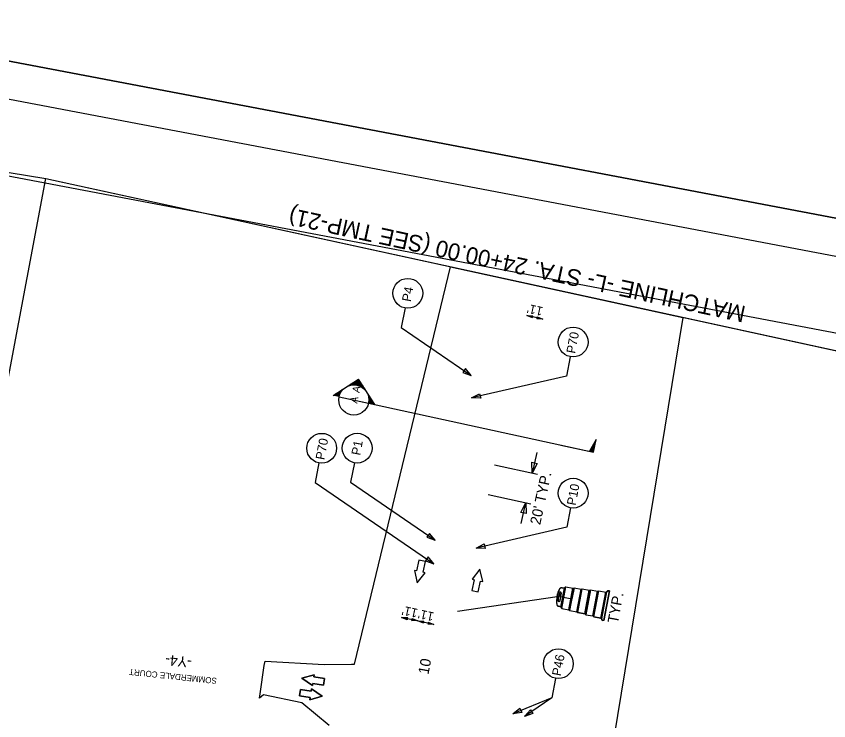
# Model space of a CAD drawing. Extents: x 1615680 to 1617075, y 898420 to 901168.
# Drawn here: x 1616157 to 1616696, y 900701 to 901168 of the extents above; entities that cross this region are included whole.
import ezdxf

# ---------------------------------------------------------------- set-up
doc = ezdxf.new("R2010")
doc.units = 0
for name, color, linetype in [('Default', 7, 'Continuous'), ('DEV BORDER CELL', 7, 'Continuous'), ('DEV DIRECTION OF TRAFFIC FLOW ARROW CELL', 7, 'Continuous'), ('DEV DRUM SECTIONAL VIEW CELL', 7, 'Continuous'), ('Matchline', 7, 'Continuous'), ('Matchline Text', 7, 'Continuous'), ('Old_Level_11', 7, 'Continuous'), ('Prop DSN Text', 7, 'Continuous'), ('Prop Horizontal Alignment Tick Label', 7, 'Continuous'), ('Scratch_Level_0', 7, 'Continuous'), ('Scratch_Level_5', 7, 'Continuous'), ('Sheet Clip Boundary CELL', 7, 'Continuous'), ('Sheet Plot Border Outside CELL', 7, 'Continuous'), ('Text', 7, 'Continuous')]:
    doc.layers.add(name, color=color, linetype=linetype)

msp = doc.modelspace()

# ---------------------------------------------------------------- linework, layer by layer
at = {"layer": 'Default'}
for p, q in [((1616366.8, 900916.91), (1616383.64, 900927.73)), ((1616378.27, 900924.23), (1616378.17, 900923.73)), ((1616378.52, 900924.39), (1616378.39, 900923.77)), ((1616378.77, 900924.54), (1616378.61, 900923.82)), ((1616379.02, 900924.7), (1616378.83, 900923.86)), ((1616379.26, 900924.86), (1616379.06, 900923.91)), ((1616379.51, 900925.02), (1616379.27, 900923.91)), ((1616379.76, 900925.18), (1616379.48, 900923.91)), ((1616380.01, 900925.34), (1616379.7, 900923.91)), ((1616380.26, 900925.5), (1616379.91, 900923.91)), ((1616380.5, 900925.66), (1616380.12, 900923.91)), ((1616380.75, 900925.82), (1616380.34, 900923.91)), ((1616381, 900925.98), (1616380.55, 900923.91)), ((1616381.25, 900926.14), (1616380.76, 900923.91)), ((1616381.5, 900926.29), (1616380.98, 900923.91)), ((1616381.74, 900926.45), (1616381.19, 900923.91)), ((1616381.99, 900926.61), (1616381.4, 900923.89)), ((1616382.24, 900926.77), (1616381.61, 900923.87)), ((1616382.49, 900926.93), (1616381.81, 900923.85)), ((1616382.73, 900927.09), (1616382.02, 900923.82)), ((1616382.98, 900927.25), (1616382.23, 900923.8)), ((1616383.23, 900927.41), (1616382.44, 900923.77)), ((1616383.48, 900927.57), (1616382.65, 900923.75)), ((1616383.68, 900927.52), (1616382.85, 900923.72)), ((1616383.84, 900927.27), (1616383.06, 900923.68)), ((1616384, 900927.03), (1616383.26, 900923.63)), ((1616384.16, 900926.78), (1616383.46, 900923.59)), ((1616394.5, 900910.82), (1616383.64, 900927.73)), ((1616384.32, 900926.53), (1616383.67, 900923.54)), ((1616384.48, 900926.29), (1616383.87, 900923.5)), ((1616384.64, 900926.04), (1616384.07, 900923.46)), ((1616384.8, 900925.8), (1616384.25, 900923.29)), ((1616384.96, 900925.55), (1616384.44, 900923.17)), ((1616385.12, 900925.3), (1616384.63, 900923.07)), ((1616385.28, 900925.06), (1616384.82, 900922.97)), ((1616385.44, 900924.81), (1616385.01, 900922.88)), ((1616385.6, 900924.57), (1616385.21, 900922.78)), ((1616385.76, 900924.32), (1616385.4, 900922.68)), ((1616369.8, 900918.8), (1616369.27, 900916.37)), ((1616370.05, 900918.96), (1616369.48, 900916.33)), ((1616370.3, 900919.12), (1616369.68, 900916.28)), ((1616370.55, 900919.28), (1616369.88, 900916.24)), ((1616370.79, 900919.44), (1616370.09, 900916.19)), ((1616371.04, 900919.6), (1616370.29, 900916.15)), ((1616371.29, 900919.76), (1616370.49, 900916.11)), ((1616371.54, 900919.92), (1616370.7, 900916.06)), ((1616371.79, 900920.08), (1616371.25, 900917.61)), ((1616372.03, 900920.24), (1616371.68, 900918.61)), ((1616372.28, 900920.4), (1616372.01, 900919.16)), ((1616372.53, 900920.57), (1616372.32, 900919.6)), ((1616372.78, 900920.73), (1616372.63, 900920.03)), ((1616373.03, 900920.89), (1616372.92, 900920.37)), ((1616373.28, 900921.05), (1616373.19, 900920.66)), ((1616373.52, 900921.21), (1616373.47, 900920.95)), ((1616377.28, 900923.59), (1616377.24, 900923.4)), ((1616377.53, 900923.75), (1616377.48, 900923.51)), ((1616377.78, 900923.91), (1616377.72, 900923.62)), ((1616378.03, 900924.07), (1616377.94, 900923.69)), ((1616385.91, 900924.07), (1616385.59, 900922.58)), ((1616386.07, 900923.83), (1616385.78, 900922.47)), ((1616386.23, 900923.58), (1616385.96, 900922.33)), ((1616386.39, 900923.34), (1616386.14, 900922.19)), ((1616386.55, 900923.09), (1616386.33, 900922.05)), ((1616386.71, 900922.84), (1616386.51, 900921.91)), ((1616386.87, 900922.6), (1616386.69, 900921.77)), ((1616387.03, 900922.35), (1616386.88, 900921.63)), ((1616387.19, 900922.11), (1616387.06, 900921.49)), ((1616387.35, 900921.86), (1616387.24, 900921.35)), ((1616387.51, 900921.61), (1616387.42, 900921.2)), ((1616387.67, 900921.37), (1616387.6, 900921.06)), ((1616387.83, 900921.12), (1616387.78, 900920.91)), ((1616367.07, 900917.03), (1616367.03, 900916.86)), ((1616367.32, 900917.19), (1616367.24, 900916.81)), ((1616367.57, 900917.35), (1616367.44, 900916.77)), ((1616367.82, 900917.51), (1616367.64, 900916.73)), ((1616368.06, 900917.67), (1616367.85, 900916.68)), ((1616368.31, 900917.83), (1616368.05, 900916.64)), ((1616368.56, 900917.99), (1616368.26, 900916.59)), ((1616368.81, 900918.15), (1616368.46, 900916.55)), ((1616369.06, 900918.31), (1616368.66, 900916.5)), ((1616369.3, 900918.48), (1616368.87, 900916.46)), ((1616369.55, 900918.64), (1616369.07, 900916.42)), ((1616370.8, 900915.99), (1616390.34, 900911.73)), ((1616370.8, 900915.98), (1616388.4, 900912.15)), ((1616390.15, 900917.42), (1616390.1, 900917.18)), ((1616390.31, 900917.17), (1616390.24, 900916.84)), ((1616390.47, 900916.92), (1616390.36, 900916.43)), ((1616390.63, 900916.68), (1616390.49, 900916.02)), ((1616390.79, 900916.43), (1616390.59, 900915.51)), ((1616391.42, 900915.43), (1616390.62, 900911.75)), ((1616391.27, 900915.68), (1616390.68, 900912.97)), ((1616390.95, 900916.18), (1616390.69, 900914.97)), ((1616391.11, 900915.93), (1616390.78, 900914.43)), ((1616391.58, 900915.18), (1616390.83, 900911.7)), ((1616391.74, 900914.93), (1616391.03, 900911.65)), ((1616391.9, 900914.68), (1616391.23, 900911.61)), ((1616392.06, 900914.43), (1616391.43, 900911.56)), ((1616392.22, 900914.18), (1616391.64, 900911.51)), ((1616392.38, 900913.93), (1616391.84, 900911.46)), ((1616392.54, 900913.68), (1616392.04, 900911.42)), ((1616392.69, 900913.43), (1616392.25, 900911.37)), ((1616390.34, 900911.73), (1616539.62, 900879.2)), ((1616392.85, 900913.18), (1616392.45, 900911.32)), ((1616393.01, 900912.93), (1616392.65, 900911.28)), ((1616393.17, 900912.69), (1616392.85, 900911.23)), ((1616393.33, 900912.44), (1616393.06, 900911.18)), ((1616393.49, 900912.19), (1616393.26, 900911.14)), ((1616393.65, 900911.94), (1616393.46, 900911.09)), ((1616393.81, 900911.69), (1616393.67, 900911.04)), ((1616393.97, 900911.44), (1616393.87, 900910.99)), ((1616394.12, 900911.19), (1616394.07, 900910.95)), ((1616541.43, 900887.52), (1616536.99, 900879.78)), ((1616539.62, 900879.2), (1616541.43, 900887.52)), ((1616541.18, 900886.4), (1616540.89, 900886.46)), ((1616541.22, 900886.61), (1616541, 900886.65)), ((1616541.26, 900886.81), (1616541.1, 900886.84)), ((1616541.31, 900887.01), (1616541.21, 900887.03)), ((1616517.94, 900883.93), (1616539.62, 900879.2)), ((1616539.93, 900880.7), (1616537.86, 900881.16)), ((1616539.98, 900880.91), (1616537.96, 900881.35)), ((1616540.02, 900881.11), (1616538.07, 900881.54)), ((1616540.07, 900881.31), (1616538.18, 900881.72)), ((1616540.11, 900881.52), (1616538.29, 900881.91)), ((1616540.16, 900881.72), (1616538.4, 900882.1)), ((1616540.2, 900881.92), (1616538.51, 900882.29)), ((1616540.24, 900882.13), (1616538.61, 900882.48)), ((1616540.29, 900882.33), (1616538.72, 900882.67)), ((1616540.33, 900882.53), (1616538.83, 900882.86)), ((1616540.38, 900882.74), (1616538.94, 900883.05)), ((1616540.42, 900882.94), (1616539.05, 900883.24)), ((1616540.47, 900883.14), (1616539.16, 900883.43)), ((1616540.51, 900883.35), (1616539.26, 900883.62)), ((1616540.56, 900883.55), (1616539.37, 900883.81)), ((1616540.6, 900883.76), (1616539.48, 900884)), ((1616540.64, 900883.96), (1616539.59, 900884.19)), ((1616540.69, 900884.16), (1616539.7, 900884.38)), ((1616540.73, 900884.37), (1616539.81, 900884.57)), ((1616540.78, 900884.57), (1616539.91, 900884.76)), ((1616540.82, 900884.77), (1616540.02, 900884.95)), ((1616540.87, 900884.98), (1616540.13, 900885.14)), ((1616540.91, 900885.18), (1616540.24, 900885.33)), ((1616540.95, 900885.38), (1616540.35, 900885.52)), ((1616541, 900885.59), (1616540.45, 900885.71)), ((1616541.04, 900885.79), (1616540.56, 900885.9)), ((1616541.09, 900885.99), (1616540.67, 900886.09)), ((1616541.13, 900886.2), (1616540.78, 900886.27)), ((1616539.62, 900879.28), (1616537.1, 900879.83)), ((1616539.67, 900879.48), (1616537.21, 900880.02)), ((1616539.71, 900879.69), (1616537.31, 900880.21)), ((1616539.76, 900879.89), (1616537.42, 900880.4)), ((1616539.8, 900880.09), (1616537.53, 900880.59)), ((1616539.85, 900880.3), (1616537.64, 900880.78)), ((1616539.89, 900880.5), (1616537.75, 900880.97)), ((1616511.96, 900716.19), (1616493.77, 900703.78))]:
    msp.add_line(p, q, dxfattribs=at)
for points in [[(1616414.53, 900974.88), (1616412.07, 900961.94), (1616458.47, 900930.16)], [(1616524.2, 900942.56), (1616521.75, 900929.62), (1616458.75, 900915.19)], [(1616357.41, 900872.07), (1616354.95, 900859.13), (1616433.75, 900805.17)], [(1616380.92, 900872.18), (1616378.47, 900859.24), (1616434.64, 900820.78)], [(1616524.25, 900842.31), (1616521.79, 900829.37), (1616461.65, 900815.6)], [(1616514.41, 900729.13), (1616511.96, 900716.19), (1616486, 900705.66)]]:
    msp.add_lwpolyline(points, dxfattribs=at)
for points in [[(1616499.07, 900968.32), (1616495.26, 900969.86), (1616499.39, 900969.7), (1616498.73, 900969.1)], [(1616502.2, 900969.07), (1616506.01, 900967.53), (1616501.88, 900967.69), (1616502.54, 900968.28)], [(1616452.81, 900932.16), (1616458.47, 900930.16), (1616454.56, 900934.72)], [(1616464.74, 900914.97), (1616458.75, 900915.19), (1616464.05, 900918)], [(1616428.98, 900822.77), (1616434.64, 900820.78), (1616430.73, 900825.33)], [(1616467.65, 900815.38), (1616461.65, 900815.6), (1616466.96, 900818.41)], [(1616428.09, 900807.16), (1616433.75, 900805.17), (1616429.85, 900809.72)], [(1616416.04, 900768.05), (1616412.23, 900769.59), (1616416.36, 900769.43), (1616415.7, 900768.84)], [(1616419.17, 900768.8), (1616422.98, 900767.26), (1616418.85, 900767.42), (1616419.5, 900768.02)], [(1616426.79, 900765.73), (1616422.98, 900767.26), (1616427.11, 900767.11), (1616426.45, 900766.51)], [(1616429.92, 900766.48), (1616433.73, 900764.94), (1616429.6, 900765.1), (1616430.25, 900765.69)], [(1616491.95, 900706.4), (1616486, 900705.66), (1616490.78, 900709.28)], [(1616499.43, 900705.76), (1616493.77, 900703.78), (1616497.68, 900708.33)]]:
    msp.add_lwpolyline(points, close=True, dxfattribs=at)
for centre, radius in [((1616416.37, 900984.6), 9.89), ((1616526.05, 900952.29), 9.89), ((1616380.57, 900913.86), 10), ((1616359.25, 900881.79), 9.89), ((1616382.77, 900881.9), 9.89), ((1616526.09, 900852.03), 9.89), ((1616516.26, 900738.85), 9.89)]:
    msp.add_circle(centre, radius, dxfattribs=at)
at = {"layer": 'DEV BORDER CELL'}
msp.add_lwpolyline([(1616014.55, 901139.21), (1615734.74, 899665.53), (1616766.32, 899469.67), (1617046.12, 900943.35)], close=True, dxfattribs=at)
at = {"layer": 'DEV DIRECTION OF TRAFFIC FLOW ARROW CELL'}
for p, q in [((1616423.78, 900807.49), (1616422.22, 900800.46)), ((1616428.03, 900806.55), (1616423.78, 900807.49)), ((1616426.47, 900799.52), (1616428.03, 900806.55)), ((1616422.22, 900800.46), (1616420.78, 900800.78)), ((1616420.78, 900800.78), (1616422.67, 900792.42)), ((1616464.27, 900801.64), (1616459.03, 900794.86)), ((1616466.17, 900793.29), (1616464.27, 900801.64)), ((1616422.67, 900792.42), (1616427.91, 900799.2)), ((1616427.91, 900799.2), (1616426.47, 900799.52)), ((1616459.03, 900794.86), (1616460.48, 900794.54)), ((1616460.48, 900794.54), (1616458.93, 900787.51)), ((1616463.17, 900786.57), (1616464.72, 900793.6)), ((1616464.72, 900793.6), (1616466.17, 900793.29)), ((1616458.93, 900787.51), (1616463.17, 900786.57)), ((1616354.32, 900731.54), (1616346.09, 900729.18)), ((1616346.09, 900729.18), (1616354.32, 900731.54)), ((1616354.09, 900730.08), (1616354.32, 900731.54)), ((1616354.32, 900731.54), (1616354.09, 900730.08)), ((1616346.09, 900729.18), (1616353.16, 900724.33)), ((1616353.16, 900724.33), (1616346.09, 900729.18)), ((1616353.16, 900724.33), (1616353.39, 900725.79)), ((1616353.39, 900725.79), (1616353.16, 900724.33)), ((1616353.39, 900725.79), (1616360.5, 900724.64)), ((1616360.5, 900724.64), (1616353.39, 900725.79)), ((1616361.19, 900728.93), (1616354.09, 900730.08)), ((1616354.09, 900730.08), (1616361.19, 900728.93)), ((1616360.5, 900724.64), (1616361.19, 900728.93)), ((1616361.19, 900728.93), (1616360.5, 900724.64)), ((1616345.24, 900721.84), (1616344.54, 900717.55)), ((1616344.54, 900717.55), (1616345.24, 900721.84)), ((1616352.34, 900720.69), (1616345.24, 900721.84)), ((1616345.24, 900721.84), (1616352.34, 900720.69)), ((1616352.58, 900722.15), (1616352.34, 900720.69)), ((1616352.34, 900720.69), (1616352.58, 900722.15)), ((1616359.65, 900717.3), (1616352.58, 900722.15)), ((1616352.58, 900722.15), (1616359.65, 900717.3)), ((1616344.54, 900717.55), (1616351.65, 900716.4)), ((1616351.65, 900716.4), (1616344.54, 900717.55)), ((1616351.41, 900714.94), (1616359.65, 900717.3)), ((1616359.65, 900717.3), (1616351.41, 900714.94)), ((1616351.65, 900716.4), (1616351.41, 900714.94)), ((1616351.41, 900714.94), (1616351.65, 900716.4))]:
    msp.add_line(p, q, dxfattribs=at)
at = {"layer": 'DEV DRUM SECTIONAL VIEW CELL'}
for p, q in [((1616518.49, 900775.5), (1616521.23, 900789.9)), ((1616521.23, 900789.9), (1616525.84, 900789.02)), ((1616517.78, 900786.29), (1616517.71, 900786.3)), ((1616517.92, 900776.69), (1616520.26, 900789)), ((1616520.26, 900789), (1616518.82, 900789.28)), ((1616523.11, 900774.62), (1616525.84, 900789.02)), ((1616523.81, 900774.13), (1616526.68, 900789.23)), ((1616525.84, 900789.02), (1616526.68, 900789.23)), ((1616526.68, 900789.23), (1616531.3, 900788.35)), ((1616528.43, 900773.25), (1616531.3, 900788.35)), ((1616529.14, 900772.76), (1616532.13, 900788.55)), ((1616531.3, 900788.35), (1616532.13, 900788.55)), ((1616532.13, 900788.55), (1616536.75, 900787.68)), ((1616533.75, 900771.88), (1616536.75, 900787.68)), ((1616534.46, 900771.38), (1616537.59, 900787.88)), ((1616536.75, 900787.68), (1616537.59, 900787.88)), ((1616537.59, 900787.88), (1616542.21, 900787)), ((1616539.07, 900770.51), (1616542.21, 900787)), ((1616539.78, 900770.01), (1616543.04, 900787.2)), ((1616542.21, 900787), (1616543.04, 900787.2)), ((1616543.04, 900787.2), (1616547.66, 900786.33)), ((1616544.4, 900769.14), (1616547.66, 900786.33)), ((1616545.08, 900768.54), (1616548.52, 900786.63)), ((1616546.47, 900767.48), (1616550.2, 900787.11)), ((1616547.66, 900786.33), (1616548.5, 900786.53)), ((1616550.2, 900787.11), (1616549.43, 900787.25)), ((1616516.61, 900780.13), (1616516.54, 900780.14)), ((1616517.92, 900776.69), (1616516.48, 900776.96)), ((1616518.49, 900775.5), (1616523.11, 900774.62)), ((1616523.11, 900774.62), (1616523.81, 900774.13)), ((1616523.81, 900774.13), (1616528.43, 900773.25)), ((1616528.43, 900773.25), (1616529.14, 900772.76)), ((1616529.14, 900772.76), (1616533.75, 900771.88)), ((1616533.75, 900771.88), (1616534.46, 900771.38)), ((1616534.46, 900771.38), (1616539.07, 900770.51)), ((1616539.07, 900770.51), (1616539.78, 900770.01)), ((1616539.78, 900770.01), (1616544.4, 900769.14)), ((1616544.4, 900769.14), (1616545.1, 900768.64)), ((1616546.47, 900767.48), (1616545.7, 900767.62))]:
    msp.add_line(p, q, dxfattribs=at)
for points in [[(1616526.68, 900789.23), (1616525.25, 900781.68), (1616517.55, 900783.14), (1616517.68, 900783.79), (1616517.8, 900784.23), (1616517.89, 900784.61), (1616517.99, 900784.93), (1616518.1, 900785.28), (1616518.19, 900785.57), (1616518.23, 900785.71), (1616518.22, 900785.84), (1616518.17, 900785.99), (1616518.07, 900786.12), (1616517.97, 900786.22), (1616517.85, 900786.27), (1616517.71, 900786.3), (1616517.53, 900786.31), (1616517.36, 900786.25), (1616517.26, 900786.19), (1616517.19, 900786.1), (1616517.13, 900786.03), (1616517.09, 900785.94), (1616517.01, 900785.69), (1616516.92, 900785.43), (1616516.85, 900785.18), (1616516.76, 900784.91), (1616516.67, 900784.57), (1616516.58, 900784.2), (1616516.51, 900783.91), (1616516.46, 900783.66), (1616516.4, 900783.36), (1616515.43, 900783.54), (1616515.52, 900783.99), (1616515.6, 900784.34), (1616515.72, 900784.83), (1616515.81, 900785.16), (1616515.92, 900785.53), (1616516.05, 900785.94), (1616516.23, 900786.42), (1616516.41, 900786.89), (1616516.64, 900787.44), (1616516.85, 900787.89), (1616517.04, 900788.29), (1616517.14, 900788.47), (1616517.24, 900788.63), (1616517.36, 900788.79), (1616517.52, 900788.95), (1616517.67, 900789.04), (1616517.85, 900789.15), (1616518.03, 900789.22), (1616518.23, 900789.28), (1616518.4, 900789.3), (1616518.6, 900789.31), (1616518.75, 900789.29), (1616518.82, 900789.28), (1616520.26, 900789), (1616520.44, 900789.26), (1616520.56, 900789.39), (1616520.7, 900789.52), (1616520.84, 900789.65), (1616521.04, 900789.79), (1616521.15, 900789.86), (1616521.23, 900789.9), (1616525.84, 900789.02)], [(1616528.43, 900773.25), (1616531.3, 900788.35), (1616532.13, 900788.55), (1616536.75, 900787.68), (1616537.59, 900787.88), (1616534.46, 900771.38), (1616533.75, 900771.88), (1616529.14, 900772.76)], [(1616539.07, 900770.51), (1616542.21, 900787), (1616543.04, 900787.2), (1616547.66, 900786.33), (1616548.5, 900786.53), (1616548.53, 900786.72), (1616548.58, 900786.83), (1616548.67, 900786.97), (1616548.78, 900787.09), (1616548.87, 900787.15), (1616549, 900787.22), (1616549.15, 900787.26), (1616549.26, 900787.27), (1616549.36, 900787.27), (1616549.43, 900787.25), (1616550.2, 900787.11), (1616546.47, 900767.48), (1616545.7, 900767.62), (1616545.6, 900767.65), (1616545.48, 900767.7), (1616545.37, 900767.77), (1616545.29, 900767.85), (1616545.23, 900767.92), (1616545.14, 900768.05), (1616545.1, 900768.18), (1616545.07, 900768.33), (1616545.06, 900768.41), (1616545.08, 900768.54), (1616545.1, 900768.64), (1616544.4, 900769.14), (1616539.78, 900770.01)], [(1616523.81, 900774.13), (1616525.25, 900781.68), (1616517.55, 900783.14), (1616517.48, 900782.77), (1616517.44, 900782.48), (1616517.39, 900782.19), (1616517.36, 900781.87), (1616517.32, 900781.53), (1616517.29, 900781.18), (1616517.27, 900780.81), (1616517.25, 900780.55), (1616517.2, 900780.42), (1616517.13, 900780.31), (1616517.02, 900780.21), (1616516.91, 900780.16), (1616516.79, 900780.12), (1616516.69, 900780.12), (1616516.47, 900780.16), (1616516.37, 900780.21), (1616516.25, 900780.3), (1616516.16, 900780.42), (1616516.1, 900780.58), (1616516.1, 900780.7), (1616516.11, 900780.98), (1616516.14, 900781.37), (1616516.21, 900782.16), (1616516.29, 900782.72), (1616516.35, 900783.14), (1616516.4, 900783.36), (1616515.43, 900783.54), (1616515.35, 900783.14), (1616515.27, 900782.62), (1616515.2, 900782.08), (1616515.16, 900781.51), (1616515.13, 900780.97), (1616515.11, 900780.37), (1616515.12, 900779.68), (1616515.14, 900779.28), (1616515.19, 900778.62), (1616515.22, 900778.33), (1616515.24, 900778.15), (1616515.31, 900777.95), (1616515.39, 900777.75), (1616515.55, 900777.52), (1616515.71, 900777.35), (1616515.86, 900777.23), (1616516.04, 900777.12), (1616516.23, 900777.03), (1616516.48, 900776.96), (1616517.92, 900776.69), (1616517.95, 900776.54), (1616518, 900776.38), (1616518.08, 900776.17), (1616518.18, 900775.96), (1616518.29, 900775.78), (1616518.49, 900775.5), (1616523.11, 900774.62)]]:
    msp.add_lwpolyline(points, close=True, dxfattribs=at)
for centre, radius, start, end in [((1616522.53, 900787.53), 2.71, 118.7358, 146.9434), ((1616532.8, 900780.24), 17.69, 152.3001, 186.1986), ((1616533.78, 900780.06), 17.69, 160.5754, 177.9234), ((1616517.61, 900785.76), 0.548, 79.2494, 160.5754), ((1616518.53, 900787.74), 1.57, 79.2494, 152.3001), ((1616534.93, 900779.84), 17.69, 161.1006, 177.3981), ((1616517.67, 900785.75), 0.548, 341.1006, 79.2494), ((1616549.29, 900786.48), 0.783, 79.2494, 169.2494), ((1616516.64, 900780.68), 0.548, 177.9234, 259.2494), ((1616516.71, 900780.67), 0.548, 259.2494, 357.3981), ((1616516.77, 900778.5), 1.57, 186.1986, 259.2494), ((1616520.57, 900777.23), 2.71, 191.5554, 219.7629), ((1616545.85, 900768.39), 0.783, 169.2494, 259.2494)]:
    msp.add_arc(centre, radius, start, end, dxfattribs=at)
at = {"layer": 'Matchline'}
msp.add_line((1616176.29, 901060.7), (1616775.18, 900930.23), dxfattribs=at)
at = {"layer": 'Old_Level_11'}
for p, q in [((1616506.01, 900967.53), (1616495.26, 900969.86)), ((1616433.73, 900764.94), (1616412.23, 900769.59))]:
    msp.add_line(p, q, dxfattribs=at)
at = {"layer": 'Prop DSN Text'}
msp.add_line((1616449.29, 900773.75), (1616515.43, 900783.54), dxfattribs=at)
at = {"layer": 'Scratch_Level_0'}
msp.add_lwpolyline([(1616054.34, 901080.76), (1615793.19, 899705.33), (1616726.52, 899528.12), (1616890.46, 900391.55), (1616774.26, 900413.61), (1616871.48, 900925.61)], close=True, dxfattribs=at)
at = {"layer": 'Scratch_Level_5'}
msp.add_lwpolyline([(1616364.12, 900697.77), (1616346.17, 900712.92), (1616320.68, 900718.26), (1616317.92, 900716.06), (1616318.38, 900718.79), (1616321.17, 900737.64), (1616321.64, 900740.44), (1616360.99, 900738.34), (1616378.95, 900738.53), (1616380.95, 900738.45), (1616444.67, 901002.24), (1616598.93, 900968.63), (1616553.12, 900689.68)], dxfattribs=at)
at = {"layer": 'Sheet Clip Boundary CELL'}
for points in [[(1616176.29, 901060.7), (1616848.46, 900914.27), (1616896.28, 900812.91), (1616872.94, 900688.21), (1616835.87, 900695.21), (1616753.94, 900262.18), (1616898.09, 900233.43), (1616734.79, 899562.1), (1616202.98, 899609.43), (1616198.71, 899647.14), (1615822.69, 899825.07), (1616054.34, 901080.76)], [(1616176.29, 901060.7), (1616914, 900899.99), (1616896.28, 900812.91), (1616872.94, 900688.21), (1616835.87, 900695.21), (1616753.94, 900262.18), (1616898.09, 900233.43), (1616747.89, 899480.25), (1615915.8, 899646.19), (1615751.76, 899738.03), (1615981.58, 900932.46), (1616145.94, 900899.57)]]:
    msp.add_lwpolyline(points, close=True, dxfattribs=at)
at = {"layer": 'Sheet Plot Border Outside CELL'}
for points in [[(1616760.47, 899304.87), (1615679.78, 899510.06), (1615994.65, 901168.43), (1617075.34, 900963.24)], [(1616760.47, 899304.87), (1617075.34, 900963.24), (1615994.65, 901168.43), (1615679.78, 899510.06)]]:
    msp.add_lwpolyline(points, close=True, dxfattribs=at)
at = {"layer": 'Text'}
for p, q in [((1616501.9, 900878.97), (1616498.93, 900865.29)), ((1616473.98, 900870.72), (1616502.35, 900864.54)), ((1616469.73, 900851.17), (1616498.09, 900845)), ((1616491.66, 900831.91), (1616494.67, 900845.74))]:
    msp.add_line(p, q, dxfattribs=at)
for points in [[(1616502.13, 900871.75), (1616498.93, 900865.29), (1616498.71, 900872.5)], [(1616491.48, 900839.28), (1616494.67, 900845.74), (1616494.9, 900838.53)]]:
    msp.add_lwpolyline(points, close=True, dxfattribs=at)

# ---------------------------------------------------------------- texts
at = {"layer": 'Default'}
for s, height, rotation, p in [('P4', 6, 79.2493, (1616418.3, 900978.67)), ("11'", 6, 167.7822, (1616506.49, 900975.32)), ('P70', 6, 79.2493, (1616527.38, 900944.32)), ('A', 5, 77.7132, (1616384.26, 900918.24)), ('A', 5, 77.7132, (1616382.74, 900911.25)), ('P70', 6, 79.2494, (1616360.98, 900873.75)), ('P1', 6, 79.2493, (1616384.76, 900876.76)), ('P10', 6, 79.2494, (1616527.68, 900843.54)), ('TYP.', 7, 79.2494, (1616555.69, 900765.18)), ("11'", 6, 167.7822, (1616423.46, 900775.06)), ("11'", 6, 167.7822, (1616434.21, 900772.73)), ('P46', 6, 79.2494, (1616517.85, 900730.36)), ('SOMMERDALE COURT', 4, 174.0116, (1616289.9, 900729.34))]:
    msp.add_text(s, height=height, rotation=rotation, dxfattribs=at).set_placement(p)
at = {"layer": 'Matchline Text'}
msp.add_text('MATCHLINE -L- STA. 24+00.00 (SEE TMP-21)', height=11, rotation=167.7956, dxfattribs=at).set_placement((1616641.18, 900975.9))
at = {"layer": 'Prop Horizontal Alignment Tick Label'}
for s, rotation, p in [('-Y4-', 174.2004, (1616273.35, 900743.12)), ('10', 79.16, (1616430.05, 900731.32))]:
    msp.add_text(s, height=7, rotation=rotation, dxfattribs=at).set_placement(p)
at = {"layer": 'Text'}
msp.add_text("20' TYP.", height=7, rotation=77.7212, dxfattribs=at).set_placement((1616504.2, 900830.6))

doc.saveas('drawing.dxf')
